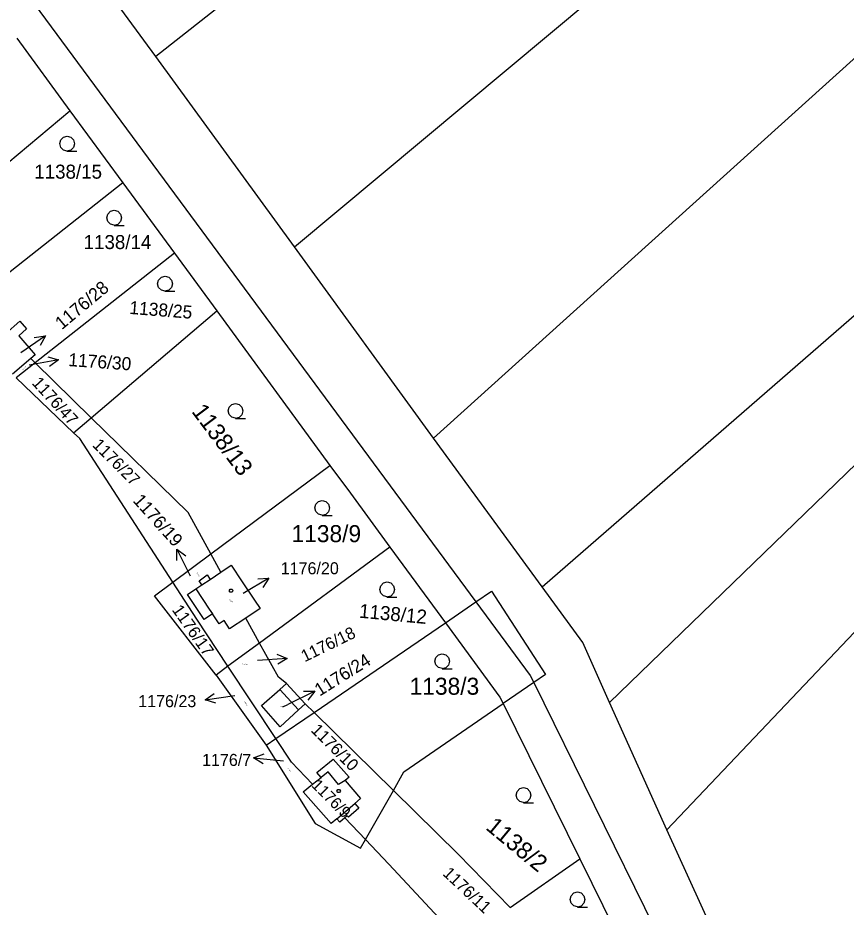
# Model space of a CAD drawing. Extents: x -621797 to -620972, y -1175539 to -1174697.
# Drawn here: x -621437.2 to -621354.5, y -1175451.4 to -1175362.6 of the extents above; entities that cross this region are included whole.
import ezdxf

# ---------------------------------------------------------------- set-up
doc = ezdxf.new("R2010")
doc.units = 0
for name, color, linetype in [('INZ mimo EON - nadz', 7, 'Continuous'), ('Rozvod plynu EON', 7, 'Continuous'), ('SDEL EON', 7, 'Continuous'), ('SDEL EON - popis', 7, 'Continuous'), ('Silnoproud EON', 7, 'Continuous'), ('Silnoproud EON - popis', 7, 'Continuous')]:
    doc.layers.add(name, color=color, linetype=linetype)

msp = doc.modelspace()

# ---------------------------------------------------------------- linework, layer by layer
at = {"layer": 'INZ mimo EON - nadz'}
for p, q in [((-621434.492, -1175394.35), (-621436.95, -1175396.07)), ((-621433.166, -1175396.769), (-621436.12, -1175397.29)), ((-621421.371, -1175415.667), (-621420.01, -1175418.34)), ((-621412.148, -1175418.546), (-621414.72, -1175420.09)), ((-621410.317, -1175426.571), (-621413.31, -1175426.78)), ((-621407.583, -1175429.855), (-621410.28, -1175431.17)), ((-621418.531, -1175430.696), (-621415.56, -1175430.28)), ((-621410.77, -1175431.41), (-621410.28, -1175431.17)), ((-621413.684, -1175436.486), (-621410.7, -1175436.8))]:
    msp.add_line(p, q, dxfattribs=at)
for points in [[(-621435.598, -1175394.514), (-621434.492, -1175394.35), (-621435.025, -1175395.333)], [(-621434.237, -1175396.45), (-621433.166, -1175396.769), (-621434.064, -1175397.435)], [(-621421.363, -1175416.785), (-621421.371, -1175415.667), (-621420.472, -1175416.331)], [(-621413.263, -1175418.632), (-621412.148, -1175418.546), (-621412.748, -1175419.489)], [(-621411.35, -1175426.142), (-621410.317, -1175426.571), (-621411.28, -1175427.14)], [(-621408.701, -1175429.844), (-621407.583, -1175429.855), (-621408.263, -1175430.743)], [(-621417.471, -1175431.053), (-621418.531, -1175430.696), (-621417.61, -1175430.062)], [(-621412.741, -1175437.088), (-621413.684, -1175436.486), (-621412.637, -1175436.094)]]:
    msp.add_lwpolyline(points, dxfattribs=at)
at = {"layer": 'Rozvod plynu EON'}
for points in [[(-621415.84, -1175419.67), (-621415.75, -1175419.82), (-621415.84, -1175419.97), (-621416.02, -1175419.97), (-621416.11, -1175419.82), (-621416.02, -1175419.67)], [(-621405.09, -1175439.68), (-621405, -1175439.83), (-621405.09, -1175439.98), (-621405.27, -1175439.98), (-621405.36, -1175439.83), (-621405.27, -1175439.68)]]:
    msp.add_lwpolyline(points, close=True, dxfattribs=at)
at = {"layer": 'SDEL EON'}
for points in [[(-621432.31, -1175375.9), (-621432.69, -1175375.8), (-621432.96, -1175375.53), (-621433.06, -1175375.16), (-621432.96, -1175374.79), (-621432.69, -1175374.52), (-621432.32, -1175374.42), (-621431.95, -1175374.52), (-621431.68, -1175374.79), (-621431.58, -1175375.17), (-621431.68, -1175375.55), (-621431.95, -1175375.82), (-621432.33, -1175375.92), (-621431.33, -1175375.92)], [(-621427.6, -1175383.3), (-621427.98, -1175383.2), (-621428.25, -1175382.93), (-621428.35, -1175382.56), (-621428.25, -1175382.19), (-621427.98, -1175381.92), (-621427.61, -1175381.82), (-621427.24, -1175381.92), (-621426.97, -1175382.19), (-621426.87, -1175382.57), (-621426.97, -1175382.95), (-621427.24, -1175383.22), (-621427.62, -1175383.32), (-621426.62, -1175383.32)], [(-621422.52, -1175389.89), (-621422.9, -1175389.79), (-621423.17, -1175389.52), (-621423.27, -1175389.15), (-621423.17, -1175388.78), (-621422.9, -1175388.51), (-621422.53, -1175388.41), (-621422.16, -1175388.51), (-621421.89, -1175388.78), (-621421.79, -1175389.16), (-621421.89, -1175389.54), (-621422.16, -1175389.81), (-621422.54, -1175389.91), (-621421.54, -1175389.91)], [(-621415.49, -1175402.58), (-621415.87, -1175402.48), (-621416.14, -1175402.21), (-621416.24, -1175401.84), (-621416.14, -1175401.47), (-621415.87, -1175401.2), (-621415.5, -1175401.1), (-621415.13, -1175401.2), (-621414.86, -1175401.47), (-621414.76, -1175401.85), (-621414.86, -1175402.23), (-621415.13, -1175402.5), (-621415.51, -1175402.6), (-621414.51, -1175402.6)], [(-621406.83, -1175412.27), (-621407.21, -1175412.17), (-621407.48, -1175411.9), (-621407.58, -1175411.53), (-621407.48, -1175411.16), (-621407.21, -1175410.89), (-621406.84, -1175410.79), (-621406.47, -1175410.89), (-621406.2, -1175411.16), (-621406.1, -1175411.54), (-621406.2, -1175411.92), (-621406.47, -1175412.19), (-621406.85, -1175412.29), (-621405.85, -1175412.29)], [(-621400.34, -1175420.42), (-621400.72, -1175420.32), (-621400.99, -1175420.05), (-621401.09, -1175419.68), (-621400.99, -1175419.31), (-621400.72, -1175419.04), (-621400.35, -1175418.94), (-621399.98, -1175419.04), (-621399.71, -1175419.31), (-621399.61, -1175419.69), (-621399.71, -1175420.07), (-621399.98, -1175420.34), (-621400.36, -1175420.44), (-621399.36, -1175420.44)], [(-621394.83, -1175427.59), (-621395.21, -1175427.49), (-621395.48, -1175427.22), (-621395.58, -1175426.85), (-621395.48, -1175426.48), (-621395.21, -1175426.21), (-621394.84, -1175426.11), (-621394.47, -1175426.21), (-621394.2, -1175426.48), (-621394.1, -1175426.86), (-621394.2, -1175427.24), (-621394.47, -1175427.51), (-621394.85, -1175427.61), (-621393.85, -1175427.61)], [(-621386.71, -1175440.96), (-621387.09, -1175440.86), (-621387.36, -1175440.59), (-621387.46, -1175440.22), (-621387.36, -1175439.85), (-621387.09, -1175439.58), (-621386.72, -1175439.48), (-621386.35, -1175439.58), (-621386.08, -1175439.85), (-621385.98, -1175440.23), (-621386.08, -1175440.61), (-621386.35, -1175440.88), (-621386.73, -1175440.98), (-621385.73, -1175440.98)], [(-621381.31, -1175451.38), (-621381.69, -1175451.28), (-621381.96, -1175451.01), (-621382.06, -1175450.64), (-621381.96, -1175450.27), (-621381.69, -1175450), (-621381.32, -1175449.9), (-621380.95, -1175450), (-621380.68, -1175450.27), (-621380.58, -1175450.65), (-621380.68, -1175451.03), (-621380.95, -1175451.3), (-621381.33, -1175451.4), (-621380.33, -1175451.4)]]:
    msp.add_lwpolyline(points, dxfattribs=at)
at = {"layer": 'SDEL EON - popis'}
for p, q in [((-621418.87, -1175419.23), (-621418.04, -1175418.68)), ((-621419.46, -1175419.63), (-621418.13, -1175421.64)), ((-621391.47, -1175420.93), (-621389.92, -1175419.87)), ((-621389.92, -1175419.87), (-621384.51, -1175428.17)), ((-621394.52, -1175423.02), (-621391.47, -1175420.93)), ((-621418.13, -1175421.64), (-621417.8, -1175422.13)), ((-621384.51, -1175428.17), (-621385.7, -1175428.99)), ((-621411.07, -1175429.69), (-621409.2, -1175431.71)), ((-621385.7, -1175428.99), (-621388.75, -1175431.09)), ((-621406.23, -1175437.9), (-621406.95, -1175438.47)), ((-621405.22, -1175439.18), (-621406.23, -1175437.9)), ((-621404.54, -1175438.75), (-621405.22, -1175439.18)), ((-621405.37, -1175442.58), (-621403.58, -1175441.05))]:
    msp.add_line(p, q, dxfattribs=at)
at = {"layer": 'Silnoproud EON'}
for p, q in [((-621463.62, -1175323.23), (-621391.47, -1175420.93)), ((-621378.32, -1175330.76), (-621423.46, -1175366.47)), ((-621409.61, -1175385.46), (-621364.86, -1175348.06)), ((-621423.46, -1175366.47), (-621433.3, -1175352.97)), ((-621437.35, -1175364.64), (-621432.04, -1175371.88)), ((-621351.28, -1175364.47), (-621395.7, -1175404.56)), ((-621409.61, -1175385.46), (-621423.46, -1175366.47)), ((-621311.79, -1175366.75), (-621378.12, -1175430.97)), ((-621372.41, -1175443.7), (-621303.5, -1175371.14)), ((-621447.51, -1175384.81), (-621432.04, -1175371.88)), ((-621432.04, -1175371.88), (-621426.75, -1175379.09)), ((-621426.75, -1175379.09), (-621441.77, -1175390.92)), ((-621426.75, -1175379.09), (-621421.6, -1175386.11)), ((-621384.86, -1175419.42), (-621339.13, -1175379.66)), ((-621421.6, -1175386.11), (-621435.51, -1175397.05)), ((-621421.6, -1175386.11), (-621417.37, -1175391.87)), ((-621395.7, -1175404.56), (-621409.61, -1175385.46)), ((-621429.91, -1175402.53), (-621417.37, -1175391.87)), ((-621417.37, -1175391.87), (-621406.06, -1175407.29)), ((-621438.48, -1175394.14), (-621437.05, -1175392.89)), ((-621437.05, -1175392.89), (-621436.37, -1175393.66)), ((-621436.37, -1175393.66), (-621437.14, -1175394.34)), ((-621437.14, -1175394.34), (-621435.52, -1175396.25)), ((-621435.95, -1175396.62), (-621437.78, -1175398.19)), ((-621435.52, -1175396.25), (-621435.95, -1175396.62)), ((-621435.51, -1175397.05), (-621435.95, -1175396.62)), ((-621435.51, -1175397.05), (-621437.41, -1175398.54)), ((-621429.91, -1175402.53), (-621435.51, -1175397.05)), ((-621431.67, -1175404.03), (-621437.41, -1175398.54)), ((-621431.67, -1175404.03), (-621429.91, -1175402.53)), ((-621420.23, -1175412), (-621429.91, -1175402.53)), ((-621431.06, -1175404.61), (-621431.67, -1175404.03)), ((-621421.76, -1175418.97), (-621431.06, -1175404.61)), ((-621384.86, -1175419.42), (-621395.7, -1175404.56)), ((-621417.96, -1175416.14), (-621406.06, -1175407.29)), ((-621406.06, -1175407.29), (-621404.02, -1175410.07)), ((-621404.02, -1175410.07), (-621400.06, -1175415.47)), ((-621417.96, -1175416.14), (-621420.23, -1175412)), ((-621400.06, -1175415.47), (-621413.09, -1175425.04)), ((-621400.06, -1175415.47), (-621394.52, -1175423.02)), ((-621421.76, -1175418.97), (-621417.96, -1175416.14)), ((-621416.96, -1175417.96), (-621417.96, -1175416.14)), ((-621416.96, -1175417.96), (-621415.94, -1175417.27)), ((-621415.94, -1175417.27), (-621414.82, -1175418.93)), ((-621419.13, -1175418.84), (-621418.33, -1175418.24)), ((-621418.33, -1175418.24), (-621418.04, -1175418.68)), ((-621418.04, -1175418.68), (-621416.96, -1175417.96)), ((-621423.57, -1175420.31), (-621421.76, -1175418.97)), ((-621419.37, -1175422.66), (-621421.76, -1175418.97)), ((-621418.87, -1175419.23), (-621419.13, -1175418.84)), ((-621414.82, -1175418.93), (-621413.59, -1175420.76)), ((-621420.29, -1175420.18), (-621419.46, -1175419.63)), ((-621419.46, -1175419.63), (-621418.87, -1175419.23)), ((-621380.81, -1175424.98), (-621384.86, -1175419.42)), ((-621417.43, -1175428.23), (-621423.57, -1175420.31)), ((-621418.9, -1175422.27), (-621420.29, -1175420.18)), ((-621413.59, -1175420.76), (-621413.03, -1175421.59)), ((-621391.47, -1175420.93), (-621386.05, -1175428.28)), ((-621413.03, -1175421.59), (-621414.46, -1175422.54)), ((-621416.25, -1175427.36), (-621419.37, -1175422.66)), ((-621418.63, -1175422.68), (-621418.9, -1175422.27)), ((-621417.8, -1175422.13), (-621418.63, -1175422.68)), ((-621417.13, -1175423.12), (-621417.8, -1175422.13)), ((-621414.46, -1175422.54), (-621416.08, -1175423.62)), ((-621413.09, -1175425.04), (-621414.46, -1175422.54)), ((-621416.63, -1175422.79), (-621417.13, -1175423.12)), ((-621416.08, -1175423.62), (-621416.63, -1175422.79)), ((-621407.65, -1175431.97), (-621394.52, -1175423.02)), ((-621394.52, -1175423.02), (-621389.07, -1175430.45)), ((-621413.09, -1175425.04), (-621416.25, -1175427.36)), ((-621411.21, -1175428.46), (-621413.09, -1175425.04)), ((-621378.12, -1175430.97), (-621380.81, -1175424.98)), ((-621416.25, -1175427.36), (-621417.43, -1175428.23)), ((-621411.46, -1175434.57), (-621416.25, -1175427.36)), ((-621417.43, -1175428.23), (-621412.43, -1175435.23)), ((-621410.41, -1175429.08), (-621411.21, -1175428.46)), ((-621386.05, -1175428.28), (-621385.7, -1175428.99)), ((-621412.9, -1175431.26), (-621411.07, -1175429.69)), ((-621411.07, -1175429.69), (-621410.41, -1175429.08)), ((-621410.41, -1175429.08), (-621408.54, -1175431.11)), ((-621385.7, -1175428.99), (-621367.39, -1175466.13)), ((-621389.07, -1175430.45), (-621388.75, -1175431.09)), ((-621411.02, -1175433.4), (-621412.9, -1175431.26)), ((-621408.54, -1175431.11), (-621409.2, -1175431.71)), ((-621407.65, -1175431.97), (-621408.54, -1175431.11)), ((-621398.66, -1175437.89), (-621388.75, -1175431.09)), ((-621388.75, -1175431.09), (-621381.1, -1175446.59)), ((-621372.41, -1175443.7), (-621378.12, -1175430.97)), ((-621411.46, -1175434.57), (-621407.65, -1175431.97)), ((-621409.2, -1175431.71), (-621411.02, -1175433.4)), ((-621399.72, -1175439.76), (-621407.65, -1175431.97)), ((-621412.43, -1175435.23), (-621411.46, -1175434.57)), ((-621409.89, -1175436.94), (-621411.46, -1175434.57)), ((-621412.43, -1175435.23), (-621407.52, -1175443.06)), ((-621407.79, -1175439.13), (-621409.89, -1175436.94)), ((-621407.36, -1175437.95), (-621405.75, -1175436.63)), ((-621405.75, -1175436.63), (-621404.15, -1175438.44)), ((-621407.79, -1175439.13), (-621406.95, -1175438.47)), ((-621406.95, -1175438.47), (-621407.36, -1175437.95)), ((-621404.15, -1175438.44), (-621404.54, -1175438.75)), ((-621399.72, -1175439.76), (-621398.66, -1175437.89)), ((-621408.75, -1175439.89), (-621407.79, -1175439.13)), ((-621404.54, -1175438.75), (-621403, -1175440.55)), ((-621405.93, -1175443.07), (-621408.75, -1175439.89)), ((-621402.5, -1175444.67), (-621399.72, -1175439.76)), ((-621393.26, -1175446.12), (-621399.72, -1175439.76)), ((-621403, -1175440.55), (-621403.58, -1175441.05)), ((-621403.58, -1175441.05), (-621403.16, -1175441.53)), ((-621404.34, -1175442.29), (-621404.58, -1175442.49)), ((-621404.22, -1175442.43), (-621404.34, -1175442.29)), ((-621403.16, -1175441.53), (-621404.22, -1175442.43)), ((-621407.52, -1175443.06), (-621402.99, -1175445.53)), ((-621405.37, -1175442.58), (-621405.93, -1175443.07)), ((-621405.08, -1175442.92), (-621405.37, -1175442.58)), ((-621404.58, -1175442.49), (-621405.08, -1175442.92)), ((-621402.5, -1175444.67), (-621404.58, -1175442.49)), ((-621361.77, -1175466.98), (-621372.41, -1175443.7)), ((-621402.99, -1175445.53), (-621402.5, -1175444.67)), ((-621400.18, -1175447.11), (-621402.5, -1175444.67)), ((-621388.05, -1175451.44), (-621393.26, -1175446.12)), ((-621388.05, -1175451.44), (-621381.1, -1175446.59)), ((-621381.1, -1175446.59), (-621379.9, -1175449.03)), ((-621392.7, -1175455.1), (-621400.18, -1175447.11)), ((-621379.9, -1175449.03), (-621374.84, -1175459.27))]:
    msp.add_line(p, q, dxfattribs=at)

# ---------------------------------------------------------------- texts
at = {"layer": 'INZ mimo EON - nadz'}
for s, height, rotation, p in [('1176/28', 1.3, 39.99245, (-621432.84, -1175393.797)), ('1176/30', 1.3, 355.97868, (-621432.22, -1175397.371)), ('1176/19', 1.3, 311.97552, (-621425.815, -1175410.857)), ('1176/18', 1.2, 26.01228, (-621408.588, -1175426.968)), ('1176/24', 1.28, 32.20023, (-621407.084, -1175430.395))]:
    msp.add_text(s, height=height, rotation=rotation, dxfattribs=at).set_placement(p)
for s, p in [('1176/20', (-621410.973, -1175418.17)), ('1176/23', (-621425.213, -1175431.44)), ('1176/7', (-621418.833, -1175437.31))]:
    msp.add_text(s, height=1.2, dxfattribs=at).set_placement(p)
at = {"layer": 'Silnoproud EON - popis'}
for s, height, p in [('1138/15', 1.4, (-621435.597, -1175378.66)), ('1138/14', 1.4, (-621430.667, -1175385.69)), ('1138/9', 1.7, (-621409.897, -1175414.96)), ('1138/3', 1.7, (-621398.097, -1175430.2)), ('1176/24', 0.1, (-621411.014, -1175431.41))]:
    msp.add_text(s, height=height, dxfattribs=at).set_placement(p)
for s, height, rotation, p in [('1138/25', 1.3, 355.52031, (-621426.131, -1175392.163)), ('1176/30', 0.1, 47.72738, (-621436.734, -1175397.783)), ('1176/47', 1.2, 312.31929, (-621435.903, -1175399.115)), ('1138/13', 1.7, 306.87619, (-621419.944, -1175401.924)), ('1176/27', 1.2, 315.01219, (-621429.864, -1175405.326)), ('1176/19', 0.1, 303.32386, (-621419.387, -1175418.019)), ('1176/20', 0.1, 324.92437, (-621416.211, -1175420.703)), ('1176/17', 1.2, 305.10003, (-621421.891, -1175421.727)), ('1138/12', 1.4, 354.60358, (-621403.188, -1175422.5)), ('1176/18', 0.1, 351.91068, (-621414.807, -1175427.163)), ('1176/23', 0.1, 302.40713, (-621414.638, -1175430.87)), ('1176/10', 1.2, 315.01219, (-621408.024, -1175433.816)), ('1176/7', 0.1, 303.32386, (-621410.287, -1175437.539)), ('1176/9', 1.14, 315.01219, (-621407.966, -1175439.315)), ('1138/2', 1.7, 320.398, (-621390.587, -1175443.58)), ('1176/11', 1.2, 316.78836, (-621394.868, -1175448.15))]:
    msp.add_text(s, height=height, rotation=rotation, dxfattribs=at).set_placement(p)

doc.saveas('drawing.dxf')
